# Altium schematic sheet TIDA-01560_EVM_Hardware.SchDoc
size 431 x 279 mm; Date: Not shown in title block; ApprovedBy: Not shown in title block; CheckedBy: Not shown in title block; Author: Not shown in title block; CompanyName: Not shown in title block; Engineer: Not shown in title block; Organization: Not shown in title block; Address1: Not shown in title block; Address2: Not shown in title block; Address3: Not shown in title block; Address4: Not shown in title block; DocumentNumber: 1; Revision: Use project parameter SCH_Rev; SheetNumber: 3; SheetTotal: 3; PageSetup: Record=PageOptions¦CenterHorizontal=True¦CenterVertical=True¦PrintScale=1.00¦XCorrection=1.00¦YCorrection=1.00¦PrintKind=0¦BorderSize=5000000¦LeftOffset=0¦BottomOffset=0¦Orientation=2¦PaperLength=1000¦PaperWidth=1000¦Scale=100¦PaperSource=15¦PrintQuality=600¦MediaType=1¦DitherType=10¦PaperKind=Letter¦PrintScaleMode=1
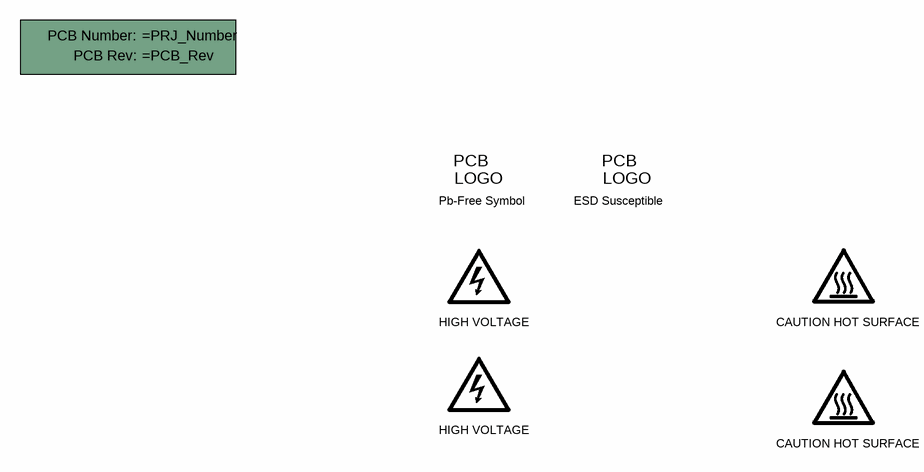
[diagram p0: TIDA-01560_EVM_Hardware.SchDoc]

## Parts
3  CAUTION HOT SURFACE  [IEC_HotSurface_small]  (no BOM)
4  CAUTION HOT SURFACE  [IEC_HotSurface_small]  (no BOM)
5  HIGH VOLTAGE  [IEC_HighVoltage_small]  (no BOM)
6  HIGH VOLTAGE  [IEC_HighVoltage_small]  (no BOM)
!PCB  Printed Circuit Board  (value not drawn)  (mechanical)
ESD  ESD Susceptible  [ESD_Overlay_small]  (no BOM)
Pb  Pb-Free Symbol  [Pb-Free_Overlay_Small]  (no BOM)

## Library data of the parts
3 4 = IEC_HotSurface: IEC 61010-1 Hot Surface Warning; SymbolCreator: a0412235
5 6 = IEC_HighVoltage: IEC 61010-1 High Voltage Warning; SymbolCreator: a0412235
!PCB = PCB: Manufacturer: Any; SymbolCreator: a0412235
ESD = ESD_Susceptible: ESD Susceptible Symbol; SymbolCreator: a0412235
Pb = Pb-Free: SymbolCreator: a0412235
